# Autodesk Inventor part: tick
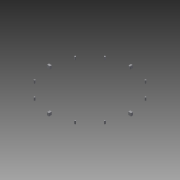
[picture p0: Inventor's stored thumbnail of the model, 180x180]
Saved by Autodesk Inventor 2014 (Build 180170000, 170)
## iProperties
Created: 2013-08
Part Number: tick
Material: Типовые
Document SubType Name: Modeling
Designer: Дмитрий
Density: 1 g/cm^3
Appearance: По умолчанию
Author: Дмитрий
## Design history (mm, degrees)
sketch "Эскиз1"
  geometry: L1 (0, 0)-(0, 92.45); L2 (0, 148)-(3.5, 148); L3 (3.5, 148)-(3.5, 138); L4 (3.5, 138)-(0, 138); L5 (0, 148)-(-3.5, 148); L6 (-3.5, 148)-(-3.5, 138); L7 (-3.5, 138)-(0, 138)
  constraints: 14 end point, 2 symmetric about line, 1 horizontal, 1 parallel, 1 perpendicular, 1 point on line, 1 vertical
  dimensions: "d0" = 7 distance between parallel lines of L3 L6; "d1" = 10 distance between parallel lines of L2 L4; "d2" = 138 distance from line of L1.start L4
sketch "Эскиз2"
  geometry: L1 (-3.5, 148)-(-3.5, 138) reference; L2 (-3.5, 138)-(0, 138) reference; C1 r 2.5 at (0, 143); 1 further point
  constraints: 1 centre point
  dimensions: "d19" = 5 diameter of C1; "d20" = 5 distance from line of C1.centre L2; "d21" = 3.5 distance from line of C1.centre L1
extrude "Выдавливание2" new body sketch "Эскиз2" distance "d22" = 5; taper "d23" = 0 deg
fillet "Сопряжение3" dims "d24" = 2
pattern_circular "Круговой массив1" dims angle "d26" = 360 deg
extrude "Выдавливание3" join sketch "Эскиз1" distance "d28" = 5; taper "d29" = 0 deg
fillet "Сопряжение4" dims "d30" = 2
pattern_circular "Круговой массив2" dims angle "d32" = 360 deg
node "Твердое тело2"
